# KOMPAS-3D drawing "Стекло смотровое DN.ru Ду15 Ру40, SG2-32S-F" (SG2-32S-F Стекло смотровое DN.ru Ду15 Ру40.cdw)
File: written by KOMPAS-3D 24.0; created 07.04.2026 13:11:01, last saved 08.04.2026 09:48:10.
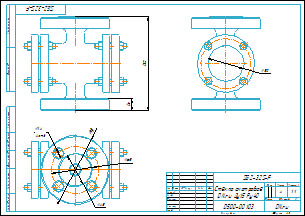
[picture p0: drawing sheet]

Document properties: Автор: Main; Форматы листов документа: A3; Полное имя файла: SG2-32S-F Стекло смотровое DN.ru Ду15 Ру40.m3d; Масса: 4; Наименование: Стекло смотровое DN.ru Ду15 Ру40; Количество листов документа: 1; Примечание: D500-00103

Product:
- Body: Тело 1  | qty 1
    Масса: 3.175709
- Part/product: Стекло смотровое DN.ru Ду15 Ру40  | designation SG2-32S-F
    Масса: 4
    Раздел спецификации: Прочие изделия
    Примечание: D500-00103

Views: Вид 1, Снизу, Проекционный вид 3
Referenced files in D:\DN.ru Аутсерс\Стекло смотровое DN.ru\Стекло смотровое DN.ru SG2-34G-F тип В ГОСТ 21836-2021 Ду100 Ру16, углеродистая сталь, фланцевое\: SG2-34G-F тип В Стекло смотровое DN.ru Ду100 Ру16.m3d, SG2-34G-F тип ВСтекло смотровое DN.ru Ду100 Ру16.cdw
Referenced files in D:\DN.ru Аутсерс\Стекло смотровое DN.ru\SG2-32S-F Стекло смотровое DN.ru Ду15 Ру40\: SG2-32S-F Стекло смотровое DN.ru Ду15 Ру40.m3d
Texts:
  SG2-32S-F
  Стекло смотровое
  DN.ru Ду15 Ру40
  Стекло смотровое DN.ru Ду15 Ру40
  SG2-32S-F Стекло смотровое DN.ru Ду15 Ру40
Dimensions and other numbers on the sheet: 0; 3; 2; 4; 130; 16; 50; 1:1; 1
